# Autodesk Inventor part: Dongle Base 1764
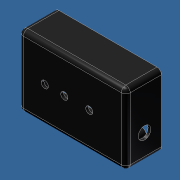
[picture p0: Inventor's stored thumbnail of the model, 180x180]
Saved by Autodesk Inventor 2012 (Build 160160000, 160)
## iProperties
Created: 2010-01
Part Number: Dongle Base 1764
Document SubType Name: Modeling
Designer: jgehrig
Density: 1 g/cm^3
Material: Default
Author: jgehrig
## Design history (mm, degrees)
sketch "Sketch1"
  geometry: L1 (-31.135, 11.158)-(45.065, 11.158); L2 (45.065, 11.158)-(45.065, -39.642); L3 (45.065, -39.642)-(-31.135, -39.642); L4 (-31.135, -39.642)-(-31.135, 11.158); 1 further point
  constraints: 8 end point, 2 parallel, 1 horizontal, 1 perpendicular
  dimensions: "d0" = 76.2 distance of L1.start L1.end; "d1" = 50.8 distance of L3.end L1.start
extrude "Extrusion1" new body sketch "Sketch1" distance "d2" = 25.4; taper "d3" = 0 deg
fillet "Fillet1" dims "d4" = 3.175
shell "Shell1" dims "d5" = 1.905
sketch "Sketch2"
  geometry: L1 (-27.96, -36.467)-(-27.96, 7.983) reference; C1 r 2.54 at (1.25, -14.242); C2 r 2.54 at (19.03, -14.242); C3 r 2.54 at (-12.72, -14.242); 1 further point
  constraints: 3 centre point
  dimensions: "d6" = 5.08 diameter of C1; "d7" = 5.08 diameter of C3; "d8" = 5.08 diameter of C2; "d9" = 15.24 distance from line of L1 C3.centre; "d10" = 13.97 distance of C3.centre C1.centre; "d11" = 17.78 distance of C1.centre C2.centre
extrude "Extrusion2" cut sketch "Sketch2" distance "d12" = 25.4; taper "d13" = 0 deg
sketch "Sketch3"
  geometry: L1 (0, -44.45)-(69.85, -44.45) reference; L2 (69.85, -44.45)-(69.85, 0) reference; L3 (71.12, 0)-(71.12, -44.45) reference; L4 (69.85, -45.72)-(0, -45.72) reference; C1 r 3.175 at (63.5, -38.1); C2 r 1.27 at (63.5, -38.1); C3 r 3.175 at (6.35, -38.1); C4 r 1.27 at (6.35, -38.1); C5 r 3.175 at (63.5, -6.35); C6 r 1.27 at (63.5, -6.35); C7 r 3.175 at (6.35, -6.35); C8 r 1.27 at (6.35, -6.35); 1 further point
  constraints: 8 centre point, 4 coincident, 1 horizontal, 1 vertical, 12 other
  dimensions: "d14" = 6.35 diameter of C1; "d15" = 2.54 diameter of C2; "d20" = 57.15 distance of C1.centre C3.centre; "d23" = 31.75 distance of C1.centre C5.centre; "d41" = 7.62 distance from line of L3 C1.centre; "d42" = 7.62 distance from line of L4 C1.centre
extrude "Extrusion3" join sketch "Sketch3" distance "d26" = 19.05; taper "d27" = 0 deg
thread "Thread1" dims "d28" = 25.4, "d29" = 0
thread "Thread2" dims "d30" = 25.4, "d31" = 0
thread "Thread3" dims "d32" = 25.4, "d33" = 0
thread "Thread4" dims "d34" = 25.4, "d35" = 0
sketch "Sketch4"
  geometry: L1 (-22.225, 0)-(-22.225, 44.45) reference; L2 (0, 0)-(-22.225, 0) reference; C1 r 4.445 at (-12.065, 14.605); 1 further point
  constraints: 1 centre point
  dimensions: "d36" = 8.89 diameter of C1; "d37" = 14.605 distance from line of L2 C1.centre; "d38" = 10.16 distance from line of L1 C1.centre
extrude "Extrusion4" cut sketch "Sketch4" distance "d39" = 6.35; taper "d40" = 0 deg
body "Solid1"
